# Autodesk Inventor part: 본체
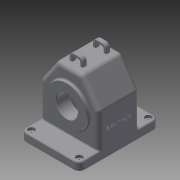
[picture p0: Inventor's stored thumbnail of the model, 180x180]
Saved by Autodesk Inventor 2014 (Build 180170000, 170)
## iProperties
Created: 2016-12
Part Number: 본체
Material: 일반
Document SubType Name: Modeling
Designer: USER
Density: 1 g/cm^3
Appearance: 기본값
Author: USER
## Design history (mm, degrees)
sketch "스케치1"
  geometry: L1 (0, 0)-(110, 0); L2 (110, 0)-(110, 80); L3 (110, 80)-(78.491, 125); L4 (78.491, 125)-(31.509, 125); L5 (31.509, 125)-(0, 80); L6 (0, 80)-(0, 0)
  constraints: 12 end point, 2 parallel, 1 horizontal, 1 perpendicular
  dimensions: "d0" = 80 distance of L1.end L2.end; "d1" = 35 deg angle of L6 L5; "d2" = 35 deg angle of L2 L3; "d3" = 125 vertical distance of L1.start L4.end; "d4" = 110 distance of L1.start L1.end; "d5" = 80 distance of L1.start L5.end
extrude "돌출1" new body sketch "스케치1" distance "d6" = 77; taper "d7" = 0 deg
node "작업 평면1"
sketch "스케치2"
  geometry: L1 (31.509, 125)-(0, 80) reference; L2 (78.491, 125)-(31.509, 125) reference; L3 (110, 80)-(78.491, 125) reference; L4 (0, 0)-(110, 0) reference; L5 (0, 80)-(0, 0) reference; L6 (31.509, 125)-(0, 80) reference; L7 (78.491, 125)-(31.509, 125) reference; L8 (110, 80)-(78.491, 125) reference; L9 (110, 0)-(110, 80) reference; L10 (105, 78.424)-(75.888, 120); L11 (75.888, 120)-(34.112, 120); L12 (34.112, 120)-(5, 78.424); L13 (5, 78.424)-(5, 0); L14 (105, 0)-(105, 78.424); L15 (5, 0)-(105, 0); 1 further point
  constraints: 12 end point, 2 point on line, 1 perpendicular, 2 other
  dimensions: "d8" = 5 distance between parallel lines of L2 L11; "d9" = 5 distance between parallel lines of L9 L14; "d10" = 5 distance between parallel lines of L5 L13
extrude "돌출2" cut sketch "스케치2" stored distance "d11" = 67; taper "d12" = 0 deg
node "작업 평면2"
sketch "스케치3"
  geometry: L1 (78.491, 125)-(31.509, 125) reference; C1 r 37.5 at (55, 65); 2 further points
  constraints: 1 centre point, 1 midpoint, 1 vertical alignment
  dimensions: "d13" = 75 diameter of C1; "d14" = 65 vertical distance of point (0, 0) C1.centre
extrude "돌출3" join sketch "스케치3" distance "d15" = 5; taper "d16" = 0 deg
sketch "스케치4"
  geometry: L1 (-78.491, 125)-(-31.509, 125) reference; C1 r 31 at (-55, 65); 2 further points
  constraints: 1 centre point, 1 midpoint, 1 vertical alignment
  dimensions: "d17" = 62 diameter of C1; "d18" = 65 vertical distance of point (-110, 0) C1.centre
extrude "돌출4" join sketch "스케치4" distance "d19" = 10; taper "d20" = 0 deg
sketch "스케치5"
  geometry: C1 r 31 at (0, 0) reference; C2 r 20 at (0, 0); 1 further point
  constraints: 1 centre point, 1 coincident
  dimensions: "d21" = 40 diameter of C2
extrude "돌출5" cut sketch "스케치5" distance "d22" = 15; taper "d23" = 0 deg
node "작업 평면4"
sketch "스케치7"
  geometry: L1 (102.5, 82)-(27.5, 82) reference; L2 (65, 72)-(65, 58); L3 (120, 72)-(78.424, 72) reference; L4 (120, 5)-(120, 72) reference; L5 (78.424, 72)-(0, 72) reference; L6 (65, 58)-(92, 58); L7 (92, 58)-(106, 72); L8 (106, 72)-(65, 72); 2 further points
  constraints: 8 end point, 2 point on line, 1 midpoint, 1 parallel, 1 perpendicular, 1 vertical alignment
  dimensions: "d28" = 27 distance of L2.end L6.end; "d29" = 45 deg angle of L6 L7; "d30" = 24 vertical distance of L1.end L2.end
revolve "회전1" sketch "스케치7" stored, may be unused: angle "d31" = 90 deg
sketch "스케치6"
  geometry: C1 r 37.5 at (0, 0) reference; C2 r 20 at (0, 0); 1 further point
  constraints: 1 centre point, 1 coincident
  dimensions: "d24" = 40 diameter of C2
extrude "돌출6" cut sketch "스케치6" distance "d25" = 24; taper "d26" = 0 deg
node "작업 평면3"
sketch "스케치9"
  geometry: L1 (-110, 113.5)-(0, 113.5); L2 (0, 113.5)-(0, -36.5); L3 (0, -36.5)-(-110, -36.5); L4 (-110, -36.5)-(-110, 113.5); L5 (-110, 0)-(-110, 77) reference; 3 further points
  constraints: 8 end point, 2 midpoint, 2 parallel, 1 coincident, 1 horizontal, 1 perpendicular, 1 vertical alignment
  dimensions: "d35" = 150 distance of L3.end L1.start; "d36" = 110 distance of L2.end L3.end
extrude "돌출8" join sketch "스케치9" distance "d37" = 15; taper "d38" = 0 deg
sketch "스케치10"
  geometry: L1 (92.5, -31.5)-(17.5, -31.5) reference; L2 (5, -108.5)-(105, -108.5) reference; L3 (5, -108.5)-(105, -108.5) reference; L4 (5, -41.5)-(5, -108.5) reference; L5 (105, -41.5)-(5, -41.5) reference; L6 (105, -108.5)-(105, -41.5) reference; 1 further point
extrude "돌출9" cut sketch "스케치10" distance "d39" = 15; taper "d40" = 0 deg
node "작업 평면5"
node "작업 평면6"
sketch "스케치11"
  geometry: L1 (-78.491, 125)-(-31.509, 125) reference; L2 (-67.5, 125)-(-67.5, 140); L3 (-67.5, 140)-(-42.5, 140); L4 (-42.5, 140)-(-42.5, 125); L5 (-62.5, 125)-(-62.5, 135); L6 (-62.5, 135)-(-47.5, 135); L7 (-47.5, 135)-(-47.5, 125); L8 (-5, 0)-(-105, 0) reference; 4 further points
  constraints: 12 end point, 5 perpendicular, 4 point on line, 3 midpoint, 2 vertical alignment, 1 parallel
  dimensions: "d42" = 25 distance of L2.end L3.end; "d43" = 15 distance of L5.end L6.end; "d44" = 140 vertical distance of L2.end L8.end; "d45" = 135 distance from line of L8.end L6
extrude "돌출10" join sketch "스케치11" distance "d46" = 8; taper "d47" = 0 deg
node "작업 평면7"
sketch "스케치12"
  geometry: L1 (-67.5, 125)-(-62.5, 125) reference; L2 (-67.5, 125)-(-67.5, 140) reference; L3 (-67.5, 140)-(-42.5, 140) reference; L4 (-42.5, 140)-(-42.5, 125) reference; L5 (-47.5, 125)-(-42.5, 125) reference; L6 (-47.5, 125)-(-47.5, 135) reference; L7 (-47.5, 135)-(-62.5, 135) reference; L8 (-62.5, 135)-(-62.5, 125) reference; 1 further point
extrude "돌출11" join sketch "스케치12" distance "d49" = 8; taper "d50" = 0 deg
fillet "모깎기1" dims "d51" = 8
fillet "모깎기2" dims "d52" = 8
fillet "모깎기3" dims "d53" = 8
fillet "모깎기4" dims "d54" = 3
fillet "모깎기5" dims "d55" = 3
fillet "모깎기6" dims "d56" = 8
fillet "모깎기7" dims "d57" = 1
fillet "모깎기8" dims "d58" = 1
fillet "모깎기9" dims "d59" = 3
fillet "모깎기10" dims "d60" = 1
fillet "모깎기11" dims "d61" = 3
fillet "모깎기12" dims "d62" = 1
fillet "모깎기13" dims "d63" = 3
fillet "모깎기14" dims "d64" = 10
chamfer "모따기1" distance "d65" = 1; stored, may be unused: second distance "d66" = 2, angle "d67" = 45 deg
fillet "모깎기15" dims "d68" = 3
sketch "스케치13"
  geometry: L1 (10, 33.5)-(100, 33.5) reference; L2 (3, 1.798)-(3, 26.5) reference; L3 (102, 3)-(8, 3) reference; L4 (107, 26.5)-(107, 1.798) reference; A1 r 7 centre (10, -103.5) between (3, -103.5) and (10, -110.5) reference; A2 r 7 centre (100, -103.5) between (100, -110.5) and (107, -103.5) reference; A3 r 7 centre (100, 26.5) between (107, 26.5) and (100, 33.5) reference; A4 r 7 centre (10, 26.5) between (10, 33.5) and (3, 26.5) reference; A5 r 11 centre (8, -8) between (8, 3) and (3, 1.798) reference; A6 r 11 centre (102, -8) between (107, 1.798) and (102, 3) reference; 5 further points
  constraints: 4 coincident
hole "구멍1" sketch "스케치13" at (10, -103.5), (100, -103.5), (100, 26.5), (10, 26.5) diameter "d69" = 5; stored, may be unused: countersink angle "d73" = 90 deg, drill point angle "d75" = 118 deg; dims "d70" = 6, "d71" = 12, "d72" = 5, "d74" = 8
sketch "스케치14"
  geometry: L1 (-8, 0)-(-8, -59.478) reference; 3 further points
  constraints: 1 other
  dimensions: "d76" = 45 vertical distance of point (95.5, -77.478) point (30.5, -32.478); "d77" = 38.5 horizontal distance of L1.end point (30.5, -32.478)
extrude "돌출12" join sketch "스케치14" distance "d78" = 0.5; taper "d79" = 0 deg
sketch "스케치15"
  geometry: C1 r 37.5 at (0, 0) reference; C2 r 21 at (0, 0) reference; A1 r 29 centre (0, 0) between (0, 29) and (29, 0); 3 further points
  constraints: 4 point on circle, 2 horizontal alignment, 2 vertical alignment, 1 centre point, 1 coincident
  dimensions: "d80" = 58 diameter of A1
hole "구멍2" sketch "스케치15" at (0, 29), (29, 0), (0, -29), (-29, 0) diameter "d81" = 2.459; stored, may be unused: countersink angle "d85" = 90 deg, drill point angle "d87" = 118 deg; dims "d82" = 6, "d83" = 4, "d84" = 2, "d86" = 8
sketch "스케치16"
  geometry: C1 r 20 at (0, 0) reference; C2 r 31 at (0, 0) reference; A1 r 26 centre (0, 0) between (0, 26) and (26, 0); 3 further points
  constraints: 4 point on circle, 2 horizontal alignment, 2 vertical alignment, 1 centre point, 1 coincident
  dimensions: "d88" = 52 diameter of A1
hole "구멍3" sketch "스케치16" at (0, 26), (26, 0), (0, -26), (-26, 0) diameter "d89" = 2.459; stored, may be unused: countersink angle "d93" = 90 deg, drill point angle "d95" = 118 deg; dims "d90" = 6, "d91" = 4, "d92" = 2, "d94" = 8
chamfer "모따기2" distance "d96" = 1; stored, may be unused: second distance "d97" = 2, angle "d98" = 45 deg
fillet "모깎기16" dims "d99" = 10
node "솔리드1"
node "투영된 루프1"
node "투영된 루프2"
node "투영된 루프3"
node "투영된 루프4"
other parameters: "d41" = 26, "d48" = -26
